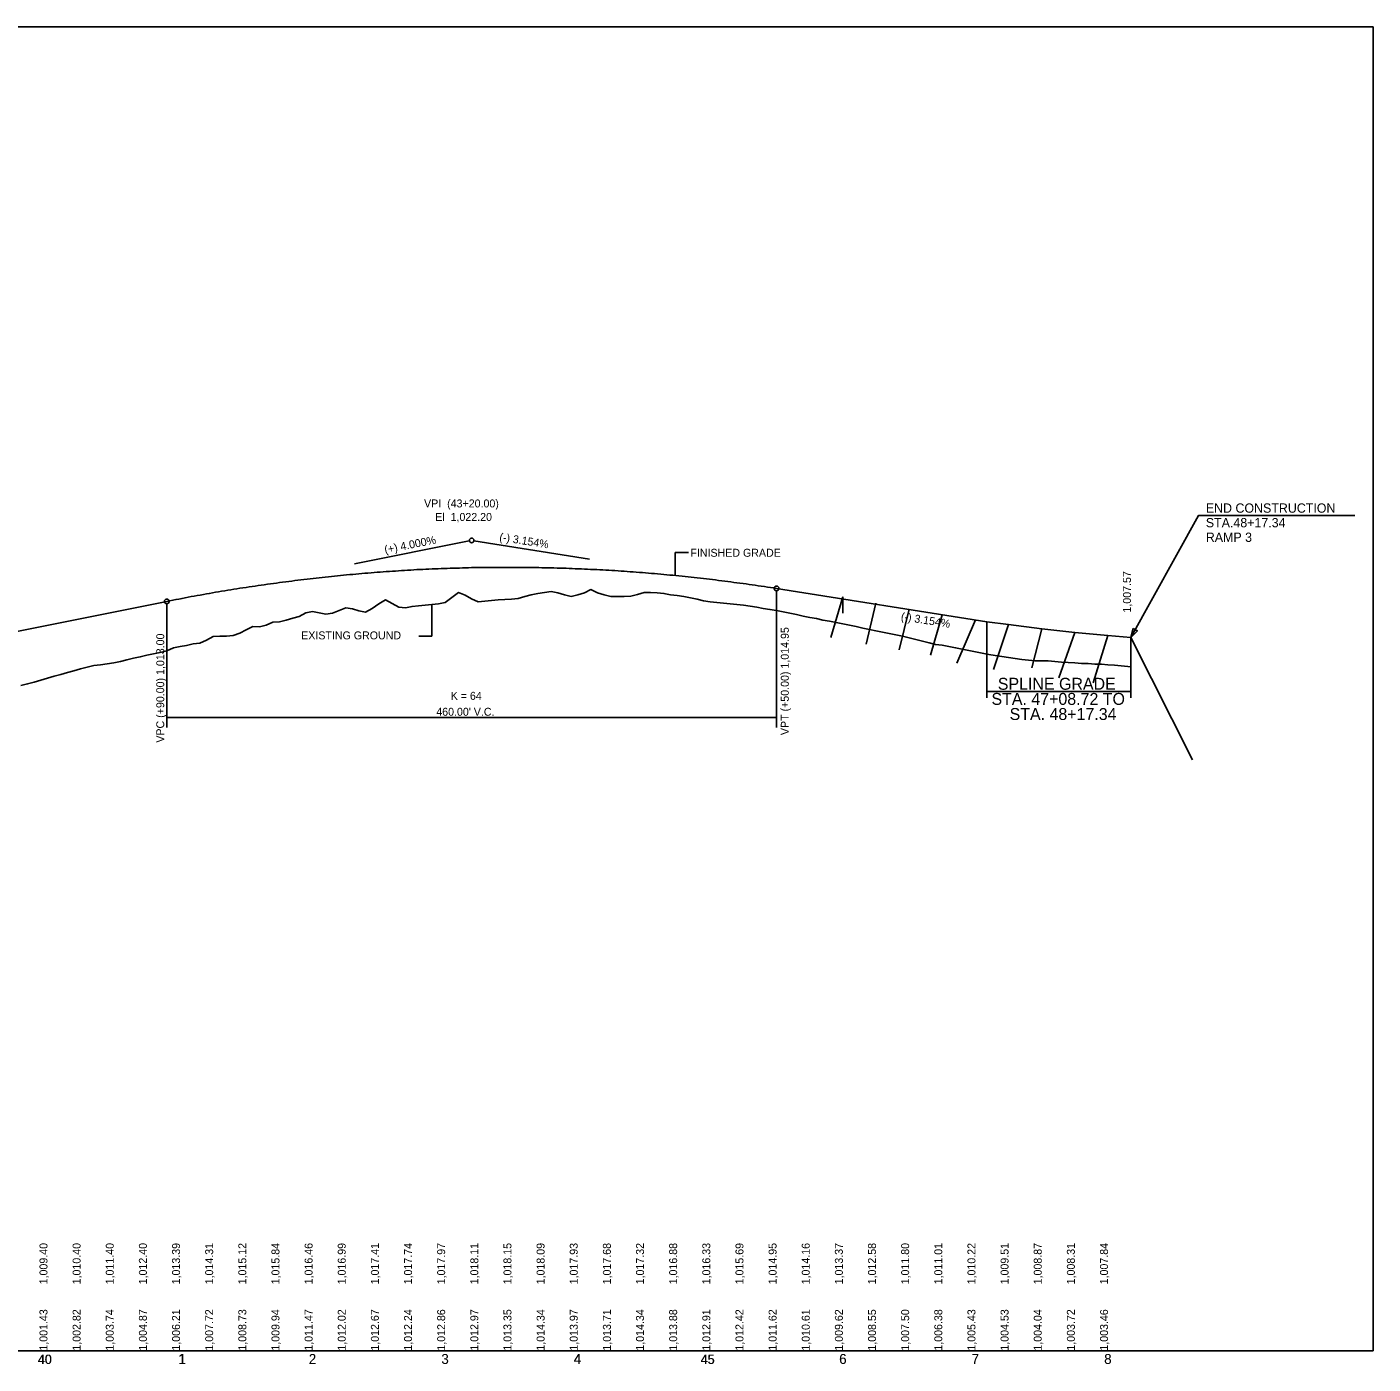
# Model space of a CAD drawing. Extents: x 1150 to 16975538, y 12057 to 12564120.
# Drawn here: x 16974522 to 16975538, y 12563110 to 12564118 of the extents above; entities that cross this region are included whole.
import ezdxf

# ---------------------------------------------------------------- set-up
doc = ezdxf.new("R2010")
doc.units = 0
for name, color, linetype in [('ANNOT_CONTOUR', 7, 'Continuous'), ('CLS_P_Shld_Gore', 7, 'Continuous'), ('Default', 7, 'Continuous'), ('RD_DDB_Profile_EX', 7, 'Continuous'), ('RD_DDB_StaTX', 7, 'Continuous'), ('RD_DDB_StripGrade', 7, 'Continuous'), ('RD_EX_Conc-ZZ', 7, 'Continuous'), ('RD_GPK_Profile_Cell', 7, 'Continuous'), ('RD_HC_CL_50', 7, 'Continuous'), ('RD_HC_TX_Sta20', 7, 'Continuous'), ('RD_PD_SuperShp1', 7, 'Continuous'), ('RD_Sketch1', 7, 'Continuous'), ('RD_Sketch7', 7, 'Continuous'), ('RD_TX_Utilities', 7, 'Continuous'), ('RD_XS_Misc_Line', 7, 'Continuous')]:
    doc.layers.add(name, color=color, linetype=linetype)

msp = doc.modelspace()

# ---------------------------------------------------------------- linework, layer by layer
at = {"layer": 'CLS_P_Shld_Gore'}
for p, q in [((16975021.3, 12563721.9), (16975011.3, 12563721.9)), ((16975011.3, 12563721.9), (16975011.3, 12563704.4))]:
    msp.add_line(p, q, dxfattribs=at)
at = {"layer": 'Default'}
msp.add_lwpolyline([(16974037.8, 12563119.9), (16975537.8, 12563119.9), (16975537.8, 12564118.1), (16974037.8, 12564118.1)], close=True, dxfattribs=at)
at = {"layer": 'RD_DDB_Profile_EX'}
for points in [[(16974537.8, 12563627.1), (16974542.8, 12563628.5), (16974547.8, 12563629.9), (16974552.8, 12563631.3), (16974557.8, 12563632.6), (16974562.8, 12563634), (16974567.8, 12563635.3), (16974572.8, 12563636.5), (16974577.8, 12563637.2), (16974582.8, 12563637.9), (16974587.8, 12563638.6), (16974592.8, 12563639.7), (16974597.8, 12563640.8), (16974602.8, 12563642), (16974607.8, 12563643.1), (16974612.8, 12563644.3), (16974617.8, 12563645.4), (16974622.8, 12563646.5), (16974627.8, 12563647.7), (16974632.8, 12563649.8), (16974637.8, 12563650.9), (16974642.8, 12563651.7), (16974647.8, 12563652.9), (16974652.8, 12563653.4), (16974657.8, 12563655.7), (16974662.8, 12563658.5), (16974667.8, 12563658.8), (16974672.8, 12563658.7), (16974677.8, 12563659.2), (16974682.8, 12563661), (16974687.8, 12563663.6), (16974692.8, 12563665.9), (16974697.8, 12563665.8), (16974702.8, 12563666.9), (16974707.8, 12563669.3), (16974712.8, 12563669.6), (16974717.8, 12563670.8), (16974722.8, 12563672.3), (16974727.8, 12563673.5), (16974732.8, 12563676.2), (16974737.8, 12563677.2), (16974742.8, 12563676.3), (16974747.8, 12563675.3), (16974752.8, 12563676.1), (16974757.8, 12563678.1), (16974762.8, 12563680), (16974767.8, 12563679.3), (16974772.8, 12563677.8), (16974777.8, 12563676.7), (16974782.8, 12563679.7), (16974787.8, 12563683.2), (16974792.8, 12563686.1), (16974797.8, 12563683.3), (16974802.8, 12563680.5), (16974807.8, 12563680.2), (16974812.8, 12563681.1), (16974817.8, 12563681.7), (16974822.8, 12563682.2), (16974827.8, 12563682.7), (16974832.8, 12563683.1), (16974837.8, 12563684.2), (16974842.8, 12563687.9), (16974847.8, 12563691.6), (16974852.8, 12563689.6), (16974857.8, 12563686.8), (16974862.8, 12563684.7), (16974867.8, 12563685.1), (16974872.8, 12563685.5), (16974877.8, 12563686), (16974882.8, 12563686.3), (16974887.8, 12563686.7), (16974892.8, 12563687.2), (16974897.8, 12563688.5), (16974902.8, 12563689.8), (16974907.8, 12563690.9), (16974912.8, 12563691.6), (16974917.8, 12563692.3), (16974922.8, 12563691.3), (16974927.8, 12563690), (16974932.8, 12563688.7), (16974937.8, 12563689.8), (16974942.8, 12563691.3), (16974947.8, 12563693.8), (16974952.8, 12563691.5), (16974957.8, 12563689.9), (16974962.8, 12563688.5), (16974967.8, 12563688.6), (16974972.8, 12563688.7), (16974977.8, 12563689), (16974982.8, 12563690.2), (16974987.8, 12563691.6), (16974992.8, 12563691.6), (16974997.8, 12563691.3), (16975002.8, 12563691), (16975007.8, 12563689.9), (16975012.8, 12563689.3), (16975017.8, 12563688.7), (16975022.8, 12563687.7), (16975027.8, 12563686.6), (16975032.8, 12563685.3), (16975037.8, 12563684.5)], [(16975037.8, 12563684.5), (16975042.8, 12563684), (16975047.8, 12563683.6), (16975052.8, 12563683.1), (16975057.8, 12563682.7), (16975062.8, 12563682), (16975067.8, 12563681.3), (16975072.8, 12563680.5), (16975077.8, 12563679.7), (16975082.8, 12563678.9), (16975087.8, 12563678), (16975092.8, 12563677), (16975097.8, 12563676), (16975102.8, 12563675), (16975107.8, 12563673.9), (16975112.8, 12563672.9), (16975117.8, 12563672), (16975122.8, 12563670.9), (16975127.8, 12563669.9), (16975132.8, 12563668.9), (16975137.8, 12563668), (16975142.8, 12563667), (16975147.8, 12563665.9), (16975152.8, 12563664.8), (16975157.8, 12563663.8), (16975162.8, 12563662.7), (16975167.8, 12563661.7), (16975172.8, 12563660.6), (16975177.8, 12563659.6), (16975182.8, 12563658.6), (16975187.8, 12563657.4), (16975192.8, 12563656.2), (16975197.8, 12563655), (16975202.8, 12563653.8), (16975207.8, 12563652.5), (16975212.8, 12563651.8), (16975217.8, 12563650.9), (16975222.8, 12563650), (16975227.8, 12563649), (16975232.8, 12563648), (16975237.8, 12563647), (16975242.8, 12563646), (16975247.8, 12563645), (16975252.8, 12563644.2), (16975257.8, 12563643.4), (16975262.8, 12563642.6), (16975267.8, 12563641.8), (16975272.8, 12563641.2), (16975277.8, 12563640.6), (16975282.8, 12563640), (16975287.8, 12563640.1), (16975292.8, 12563640), (16975297.8, 12563639.6), (16975302.8, 12563639.2), (16975307.8, 12563638.8), (16975312.8, 12563638.5), (16975317.8, 12563638.2), (16975322.8, 12563638), (16975327.8, 12563637.7), (16975332.8, 12563637.5), (16975337.8, 12563637.2), (16975342.8, 12563636.8), (16975347.8, 12563636.4), (16975352.8, 12563635.9), (16975355.1, 12563635.7)], [(16974517.8, 12563621.4), (16974522.8, 12563622.7), (16974527.8, 12563624.1), (16974532.8, 12563625.6), (16974537.8, 12563627.1)]]:
    msp.add_lwpolyline(points, dxfattribs=at)
at = {"layer": 'RD_DDB_StripGrade'}
for p, q in [((16975246.5, 12563612.2), (16975246.5, 12563669.6)), ((16975355.1, 12563612.2), (16975355.1, 12563657.6)), ((16975246.5, 12563617.1), (16975355.1, 12563617.1))]:
    msp.add_line(p, q, dxfattribs=at)
at = {"layer": 'RD_EX_Conc-ZZ'}
for p, q in [((16974769.5, 12563713.3), (16974856, 12563730.6)), ((16974946.7, 12563716.9), (16974859.5, 12563730.7))]:
    msp.add_line(p, q, dxfattribs=at)
msp.add_circle((16974857.8, 12563730.9), 1.75, dxfattribs=at)
at = {"layer": 'RD_GPK_Profile_Cell'}
msp.add_line((16973037.6, 12563119.9), (16975355.1, 12563119.9), dxfattribs=at)
at = {"layer": 'RD_HC_TX_Sta20'}
for p, q in [((16975087.8, 12563589.9), (16975087.8, 12563692.9)), ((16974627.8, 12563589.9), (16974627.8, 12563683.2)), ((16974627.8, 12563597.4), (16975087.8, 12563597.4))]:
    msp.add_line(p, q, dxfattribs=at)
for centre in [(16975087.8, 12563694.7), (16974627.8, 12563684.9)]:
    msp.add_circle(centre, 1.75, dxfattribs=at)
at = {"layer": 'RD_Sketch1'}
for p, q in [((16975137.8, 12563688.4), (16975128.8, 12563657.6)), ((16975137.8, 12563688.4), (16975137.8, 12563676.1)), ((16975162.8, 12563683.6), (16975155.4, 12563652.6)), ((16975187.8, 12563679.1), (16975180.3, 12563648.3)), ((16975212.8, 12563674.9), (16975204, 12563644.3)), ((16975237.8, 12563671), (16975223.7, 12563638.3)), ((16975262.8, 12563667.4), (16975251.5, 12563633.7)), ((16975287.8, 12563664.3), (16975280.3, 12563634.8)), ((16975312.8, 12563661.4), (16975300.8, 12563627.3)), ((16975337.8, 12563659.1), (16975326.7, 12563623.4)), ((16975355.1, 12563657.6), (16975401.5, 12563565.5))]:
    msp.add_line(p, q, dxfattribs=at)
at = {"layer": 'RD_Sketch7'}
for p, q in [((16974827.8, 12563658.8), (16974827.8, 12563682.7)), ((16974818, 12563658.8), (16974827.8, 12563658.8))]:
    msp.add_line(p, q, dxfattribs=at)
at = {"layer": 'RD_TX_Utilities'}
msp.add_line((16975524.1, 12563749.8), (16975407.6, 12563749.8), dxfattribs=at)
msp.add_lwpolyline([(16975407.6, 12563749.8), (16975406.2, 12563749.8), (16975355.1, 12563657.6)], dxfattribs=at)
msp.add_lwpolyline([(16975356.8, 12563664.4), (16975355.1, 12563657.6), (16975360, 12563662.7)], close=True, dxfattribs=at)
at = {"layer": 'RD_XS_Misc_Line'}
for p, q in [((16975087.8, 12563694.7), (16975246.5, 12563669.6)), ((16974292.8, 12563617.9), (16974627.8, 12563684.9)), ((16975246.5, 12563669.6), (16975262.8, 12563667.4)), ((16975262.8, 12563667.4), (16975287.8, 12563664.3)), ((16975287.8, 12563664.3), (16975312.8, 12563661.4)), ((16975312.8, 12563661.4), (16975337.8, 12563659.1)), ((16975337.8, 12563659.1), (16975355.1, 12563657.7))]:
    msp.add_line(p, q, dxfattribs=at)
msp.add_spline([(16974627.8, 12563684.9), (16974637, 12563686.7), (16974646.2, 12563688.5), (16974655.4, 12563690.1), (16974664.6, 12563691.8), (16974673.8, 12563693.3), (16974683, 12563694.8), (16974692.2, 12563696.2), (16974701.4, 12563697.5), (16974710.6, 12563698.8), (16974719.8, 12563700), (16974729, 12563701.2), (16974738.2, 12563702.3), (16974747.4, 12563703.3), (16974756.6, 12563704.2), (16974765.8, 12563705.1), (16974775, 12563705.9), (16974784.2, 12563706.7), (16974793.4, 12563707.4), (16974802.6, 12563708), (16974811.8, 12563708.6), (16974821, 12563709.1), (16974830.2, 12563709.5), (16974839.4, 12563709.8), (16974848.6, 12563710.1), (16974857.8, 12563710.4), (16974867, 12563710.5), (16974876.2, 12563710.6), (16974885.4, 12563710.6), (16974894.6, 12563710.6), (16974903.8, 12563710.5), (16974913, 12563710.3), (16974922.2, 12563710.1), (16974931.4, 12563709.8), (16974940.6, 12563709.4), (16974949.8, 12563709), (16974959, 12563708.5), (16974968.2, 12563708), (16974977.4, 12563707.3), (16974986.6, 12563706.6), (16974995.8, 12563705.9), (16975005, 12563705), (16975014.2, 12563704.2), (16975023.4, 12563703.2), (16975032.6, 12563702.2), (16975041.8, 12563701.1), (16975051, 12563699.9), (16975060.2, 12563698.7), (16975069.4, 12563697.4), (16975078.6, 12563696.1), (16975087.8, 12563694.7)], degree=3, dxfattribs=at)

# ---------------------------------------------------------------- texts
at = {"layer": 'ANNOT_CONTOUR'}
for s, p in [('1,001.43', (16974537.8, 12563119.9)), ('1,002.82', (16974562.8, 12563119.9)), ('1,003.74', (16974587.8, 12563119.9)), ('1,004.87', (16974612.8, 12563119.9)), ('1,006.21', (16974637.8, 12563119.9)), ('1,007.72', (16974662.8, 12563119.9)), ('1,008.73', (16974687.8, 12563119.9)), ('1,009.94', (16974712.8, 12563119.9)), ('1,011.47', (16974737.8, 12563119.9)), ('1,012.02', (16974762.8, 12563119.9)), ('1,012.67', (16974787.8, 12563119.9)), ('1,012.24', (16974812.8, 12563119.9)), ('1,012.86', (16974837.8, 12563119.9)), ('1,012.97', (16974862.8, 12563119.9)), ('1,013.35', (16974887.8, 12563119.9)), ('1,014.34', (16974912.8, 12563119.9)), ('1,013.97', (16974937.8, 12563119.9)), ('1,013.71', (16974962.8, 12563119.9)), ('1,014.34', (16974987.8, 12563119.9)), ('1,013.88', (16975012.8, 12563119.9)), ('1,012.91', (16975037.8, 12563119.9)), ('1,012.42', (16975062.8, 12563119.9)), ('1,011.62', (16975087.8, 12563119.9)), ('1,010.61', (16975112.8, 12563119.9)), ('1,009.62', (16975137.8, 12563119.9)), ('1,008.55', (16975162.8, 12563119.9)), ('1,007.50', (16975187.8, 12563119.9)), ('1,006.38', (16975212.8, 12563119.9)), ('1,005.43', (16975237.8, 12563119.9)), ('1,004.53', (16975262.8, 12563119.9)), ('1,004.04', (16975287.8, 12563119.9)), ('1,003.72', (16975312.8, 12563119.9)), ('1,003.46', (16975337.8, 12563119.9))]:
    msp.add_text(s, height=6, rotation=90, dxfattribs=at).set_placement(p)
at = {"layer": 'CLS_P_Shld_Gore'}
msp.add_text('FINISHED GRADE', height=6, dxfattribs=at).set_placement((16975022.8, 12563718.6))
at = {"layer": 'RD_DDB_StaTX'}
for s, height, p in [('40', 7, (16974530.5, 12563109.9)), ('40', 7, (16974530.8, 12563109.9)), ('1', 7.5, (16974636.4, 12563109.9)), ('1', 7.5, (16974636.8, 12563109.9)), ('2', 7.5, (16974734.9, 12563109.9)), ('2', 7.5, (16974735, 12563109.9)), ('3', 7.5, (16974834.9, 12563109.9)), ('3', 7.5, (16974835, 12563109.9)), ('4', 7.5, (16974934.7, 12563109.9)), ('4', 7.5, (16974935, 12563109.9)), ('45', 7, (16975030.5, 12563109.9)), ('45', 7, (16975030.8, 12563109.9)), ('6', 7.5, (16975135, 12563109.9)), ('6', 7.5, (16975135.1, 12563109.9)), ('7', 7.5, (16975234.9, 12563109.9)), ('7', 7.5, (16975235, 12563109.9)), ('8', 7.5, (16975334.9, 12563109.9)), ('8', 7.5, (16975335, 12563109.9))]:
    msp.add_text(s, height=height, dxfattribs=at).set_placement(p)
at = {"layer": 'RD_DDB_StripGrade'}
for s, p in [('SPLINE GRADE', (16975254.7, 12563618.3)), ('STA. 47+08.72 TO', (16975249.9, 12563606.9)), ('STA. 48+17.34', (16975263.6, 12563595.5))]:
    msp.add_text(s, height=9, dxfattribs=at).set_placement(p)
at = {"layer": 'RD_EX_Conc-ZZ'}
for s, p in [('VPI  (43+20.00)', (16974821.9, 12563755.8)), ('El  1,022.20', (16974830.3, 12563745.6))]:
    msp.add_text(s, height=6, dxfattribs=at).set_placement(p)
msp.add_text('1,007.57', height=6, rotation=90, dxfattribs=at).set_placement((16975355.1, 12563676.5))
at = {"layer": 'RD_HC_CL_50'}
for s, p in [('1,009.40', (16974537.8, 12563169.9)), ('1,010.40', (16974562.8, 12563169.9)), ('1,011.40', (16974587.8, 12563169.9)), ('1,012.40', (16974612.8, 12563169.9)), ('1,013.39', (16974637.8, 12563169.9)), ('1,014.31', (16974662.8, 12563169.9)), ('1,015.12', (16974687.8, 12563169.9)), ('1,015.84', (16974712.8, 12563169.9)), ('1,016.46', (16974737.8, 12563169.9)), ('1,016.99', (16974762.8, 12563169.9)), ('1,017.41', (16974787.8, 12563169.9)), ('1,017.74', (16974812.8, 12563169.9)), ('1,017.97', (16974837.8, 12563169.9)), ('1,018.11', (16974862.8, 12563169.9)), ('1,018.15', (16974887.8, 12563169.9)), ('1,018.09', (16974912.8, 12563169.9)), ('1,017.93', (16974937.8, 12563169.9)), ('1,017.68', (16974962.8, 12563169.9)), ('1,017.32', (16974987.8, 12563169.9)), ('1,016.88', (16975012.8, 12563169.9)), ('1,016.33', (16975037.8, 12563169.9)), ('1,015.69', (16975062.8, 12563169.9)), ('1,014.95', (16975087.8, 12563169.9)), ('1,014.16', (16975112.8, 12563169.9)), ('1,013.37', (16975137.8, 12563169.9)), ('1,012.58', (16975162.8, 12563169.9)), ('1,011.80', (16975187.8, 12563169.9)), ('1,011.01', (16975212.8, 12563169.9)), ('1,010.22', (16975237.8, 12563169.9)), ('1,009.51', (16975262.8, 12563169.9)), ('1,008.87', (16975287.8, 12563169.9)), ('1,008.31', (16975312.8, 12563169.9)), ('1,007.84', (16975337.8, 12563169.9))]:
    msp.add_text(s, height=6, rotation=90, dxfattribs=at).set_placement(p)
at = {"layer": 'RD_HC_TX_Sta20'}
for s, p in [('VPT (+50.00) 1,014.95', (16975097, 12563584.1)), ('VPC (+90.00) 1,013.00', (16974625.9, 12563578.4))]:
    msp.add_text(s, height=6, rotation=90, dxfattribs=at).set_placement(p)
for s, p in [('K = 64', (16974842, 12563610.7)), ("460.00' V.C.", (16974831.1, 12563598.7))]:
    msp.add_text(s, height=6, dxfattribs=at).set_placement(p)
at = {"layer": 'RD_PD_SuperShp1'}
for s, rotation, p in [('(+) 4.000%', 11.3099, (16974792.6, 12563720.9)), ('(-) 3.154%', 351.0392, (16974878.4, 12563730.7)), ('(-) 3.154%', 351.0392, (16975181.3, 12563670.8))]:
    msp.add_text(s, height=6, rotation=rotation, dxfattribs=at).set_placement(p)
at = {"layer": 'RD_Sketch7'}
msp.add_text('EXISTING GROUND', height=6, dxfattribs=at).set_placement((16974729.2, 12563656.3))
at = {"layer": 'RD_TX_Utilities'}
for s, p in [('END CONSTRUCTION', (16975411.6, 12563751.8)), ('STA.48+17.34 ', (16975411.6, 12563740.8)), ('RAMP 3', (16975411.6, 12563729.8))]:
    msp.add_text(s, height=7, dxfattribs=at).set_placement(p)

doc.saveas('drawing.dxf')
